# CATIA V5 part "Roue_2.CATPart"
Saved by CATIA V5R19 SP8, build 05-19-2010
Part number: Roue 2
Nomenclature: 70_R2
Bounding box of the stored display mesh (mm): x -20.76 to 20.76, y -20.76 to 20.76, z -2.4 to 8
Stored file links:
  C:\Users\rphgr\Desktop\0_Tapis_TC520B_vitesse\Roue_2.CATPart
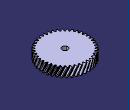
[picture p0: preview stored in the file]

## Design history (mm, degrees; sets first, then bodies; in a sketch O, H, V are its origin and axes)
External parameters (linked from other documents)
  External.Module = 0.9 mm
  External.Z = 40
  External.DiamPrimitif = 39.7216 mm {= External.ModuleApparent*External.Z}
  External.AnglePression = 20 deg
  External.x = 0
  External.DeportDenture = 0 mm {= External.x *External.ModuleApparent}
  External.DiamBase = 37.3261 mm {= External.DiamPrimitif *cos(External.AnglePression )}
  External.DiamPied = 37.4716 mm {= External.DiamPrimitif -2.5*External.Module +2*External.DeportDenture}
  External.DiamTete = 41.5216 mm {= External.DiamPrimitif +2*External.Module +2*External.DeportDenture}
  External.PhiPrimitif = 0.854 deg {= atan((sin(External.ThetaPrimitif*1rad)-External.ThetaPrimitif*cos(External.ThetaPrimitif*1rad))/(cos(External.ThetaPrimitif*1rad)+External.ThetaPrimitif*sin(External.ThetaPrimitif*1rad)))}
  External.PhiTete = 1.94 deg {= atan((sin(External.ThetaTete*1rad)-External.ThetaTete*cos(External.ThetaTete*1rad))/(cos(External.ThetaTete*1rad)+External.ThetaTete*sin(External.ThetaTete*1rad)))}
  External.PhiSymetrie = 2.25 deg {= 180*1 deg/(2*External.Z )}
  External.CongePied = 0.342 mm {= 0.38*External.Module}
  External.AlphaCopie = 9 deg {= 360*1 deg/External.Z}
  External.AlphaSymetrieCopie = 4.5 deg {= External.AlphaCopie /2}
  External.LargeurDenture = 8 mm {= External.LargeurDent}
  External.ThetaPrimitif = 0.36397 {= sqrt(abs((External.DiamPrimitif*External.DiamPrimitif)/(External.DiamBase *External.DiamBase )-1))}
  External.ThetaTete = 0.487275 {= sqrt(abs((External.DiamTete*External.DiamTete)/(External.DiamBase *External.DiamBase )-1) )}
  External.Di = 38.5239 mm {= (External.DiamBase +External.DiamPrimitif )/2}
  External.Thetai = 0.255358 {= sqrt(abs((External.Di*External.Di)/(External.DiamBase*External.DiamBase)-1))}
  External.Phii = 0.3061 deg {= atan((sin(External.Thetai*1rad)-External.Thetai*cos(External.Thetai*1rad))/(cos(External.Thetai*1rad)+External.Thetai*sin(External.Thetai*1rad)))}
  External.Dj = 40.6216 mm {= (External.DiamTete+External.DiamPrimitif)/2}
  External.Thetaj = 0.429388 {= sqrt(abs((External.Dj*External.Dj)/(External.DiamBase*External.DiamBase)-1))}
  External.Phij = 1.364 deg {= atan((sin(External.Thetaj*1rad)-External.Thetaj*cos(External.Thetaj*1rad))/(cos(External.Thetaj*1rad)+External.Thetaj*sin(External.Thetaj*1rad)))}
  External.Dk = 37.925 mm {= (External.Di+External.DiamBase)/2}
  External.Thetak = 0.179851 {= sqrt(abs((External.Dk*External.Dk)/(External.DiamBase*External.DiamBase)-1))}
  External.Phik = 0.109 deg {= atan((sin(External.Thetak*1rad)-External.Thetak*cos(External.Thetak*1rad))/(cos(External.Thetak*1rad)+External.Thetak*sin(External.Thetak*1rad)))}
  External.Dl = 39.1227 mm {= (External.DiamPrimitif+External.Di)/2}
  External.Thetal = 0.31398 {= sqrt(abs((External.Dl*External.Dl)/(External.DiamBase*External.DiamBase)-1))}
  External.Phil = 0.5585 deg {= atan((sin(External.Thetal*1rad)-External.Thetal*cos(External.Thetal*1rad))/(cos(External.Thetal*1rad)+External.Thetal*sin(External.Thetal*1rad)))}
  External.Dm = 40.1716 mm {= (External.Dj+External.DiamPrimitif)/2}
  External.Thetam = 0.397843 {= sqrt(abs((External.Dm*External.Dm)/(External.DiamBase*External.DiamBase)-1))}
  External.Phim = 1.0999 deg {= atan((sin(External.Thetam*1rad)-External.Thetam*cos(External.Thetam*1rad))/(cos(External.Thetam*1rad)+External.Thetam*sin(External.Thetam*1rad)))}
  External.Dn = 41.0716 mm {= (External.DiamTete+External.Dj)/2}
  External.Thetan = 0.459086 {= sqrt(abs((External.Dn*External.Dn)/(External.DiamBase*External.DiamBase)-1))}
  External.Phin = 1.6445 deg {= atan((sin(External.Thetan*1rad)-External.Thetan*cos(External.Thetan*1rad))/(cos(External.Thetan*1rad)+External.Thetan*sin(External.Thetan*1rad)))}
  External.AngleHelice = 25 deg
  External.ModuleApparent = 0.993 mm {= External.Module /cos(External.AngleHelice )}
  External.SensDenture = 1
  External.LargeurDent = 8 mm
Body1 (main body)
  Sketch1 "EsquisseDent" on xy-plane, origin (0, 0, 0), H (1, 0, 0), V (0, 1, 0)
    construction circle A1 centre (0, 0) radius 19.8608
    construction circle A2 centre (0, 0) radius 18.663
    construction circle A3 centre (0, 0) radius 18.7358
    construction circle A4 centre (0, 0) radius 20.7608
    point P1 (18.663, 0)
    construction line L1 (18.663, 0) -> (0, 0)
    point P2 (19.8586, 0.296)
    construction line L2 (19.8586, 0.296) -> (0, 0)
    point P3 (20.7489, 0.7028)
    construction line L3 (20.7489, 0.7028) -> (0, 0)
    construction line L4 (18.663, 0) -> (18.663, 3.9367)
    point P4 (18.663, 0)
    point P6 (17.4675, 0.296)
    construction line L5 (20.7489, 0.7028) -> (19.8586, 0.296)
    point P7 (20.3037, 0.4994)
    point P8 (17.0223, 0.4994)
    spline S1 through (17.0223, 0.4994) (17.4675, 0.296) (18.663, 0) (18.9625, 0.0361) (19.2617, 0.1029) (19.5604, 0.1907) (19.8586, 0.296) (20.0821, 0.3856) (20.305, 0.4835) (20.5273, 0.5893) (20.7489, 0.7028)
    construction line L6 (0, 0) -> (5.2667, 0.2856)
    spline S2 through (16.9765, 1.3443) (17.3971, 1.5946) (18.5536, 2.0182) (18.8552, 2.0147) (19.1598, 1.9806) (19.4664, 1.9257) (19.7742, 1.8532) (20.006, 1.7883) (20.2383, 1.7151) (20.4707, 1.6339) (20.7032, 1.545)
    arc A5 centre (19.0756, -0.2906) radius 0.342 from (19.01, 0.045) to (18.7336, -0.2854) ccw
    point P11 (18.7336, -0.2854)
    arc A6 centre (0, 0) radius 20.7608 from (20.7489, 0.7028) to (20.7032, 1.545) ccw
    point P13 (20.7032, 1.545)
    arc A7 centre (18.9323, 2.3517) radius 0.342 from (18.5929, 2.3096) to (18.9034, 2.0109) ccw
    point P15 (18.5929, 2.3096)
    construction line L7 (0, 0) -> (4.2456, 0.5668)
    construction line L8 (0, 0) -> (5.1243, -0.1249)
    point P19 (18.571, 2.4792)
    arc A8 centre (0, 0) radius 18.7358 from (18.5929, 2.3096) to (18.571, 2.4792) ccw
    point P20 (18.7302, -0.4565)
    arc A9 centre (0, 0) radius 18.7358 from (18.7302, -0.4565) to (18.7336, -0.2854) ccw
    line L9 (18.571, 2.4792) -> (0, 0)
    line L10 (18.7302, -0.4565) -> (0, 0)
    construction circle A10 centre (0, 0) radius 19.2619
    construction line L11 (0, 0) -> (2.5698, 0.0137)
    point P22 (19.2617, 0.1029)
    construction circle A11 centre (0, 0) radius 20.3108
    construction line L12 (0, 0) -> (4.0179, 0.0957)
    point P24 (20.305, 0.4835)
    point P25 (20.305, 0.4835)
    point P26 (20.2383, 1.7151)
    point P27 (19.1598, 1.9806)
    construction circle A12 centre (0, 0) radius 18.9625
    construction line L13 (0, 0) -> (48.2618, 0.0918)
    point P29 (18.8552, 2.0147)
    construction line L14 (0, 0) -> (63.8846, 3.4643)
    point P31 (18.9625, 0.0361)
    construction circle A13 centre (0, 0) radius 19.5614
    construction line L15 (0, 0) -> (57.3607, 0.5591)
    point P33 (19.5604, 0.1907)
    point P34 (19.4664, 1.9257)
    construction circle A14 centre (0, 0) radius 20.0858
    construction line L16 (0, 0) -> (65.6986, 1.2614)
    point P36 (20.0821, 0.3856)
    point P37 (20.006, 1.7883)
    construction circle A15 centre (0, 0) radius 20.5358
    axis line L17 (0, 0) -> (59.3265, 1.7033)
    point P39 (20.4707, 1.6339)
    point P40 (20.5273, 0.5893)
    point P42 (17.0223, 0.4994)
    point P43 (17.4675, 0.296)
    point P44 (18.663, 0)
    point P45 (19.8586, 0.296)
    point P46 (20.7489, 0.7028)
    point P47 (20.7032, 1.545)
    point P48 (16.9765, 1.3443)
    point P49 (19.7742, 1.8532)
    point P50 (18.5536, 2.0182)
    point P51 (17.3971, 1.5946)
    point P52 (19.2617, 0.1029)
    point P53 (20.305, 0.4835)
    point P54 (19.1598, 1.9806)
    point P55 (20.2383, 1.7151)
    point P56 (18.9625, 0.0361)
    point P57 (18.8552, 2.0147)
    point P58 (19.5604, 0.1907)
    point P59 (19.4664, 1.9257)
    point P60 (20.0821, 0.3856)
    point P61 (20.006, 1.7883)
    point P62 (20.5273, 0.5893)
    point P63 (20.4707, 1.6339)
    radius A1 = 19.8608 {= External.DiamPrimitif /2}
    radius A2 = 18.663 {= External.DiamBase /2}
    radius A3 = 18.7358 {= External.DiamPied /2}
    radius A4 = 20.7608 {= External.DiamTete /2}
    angle L2 L1 = 0.854 {= External.PhiPrimitif}
    angle L3 L1 = 1.94 {= External.PhiTete}
    angle L4 L1 = 90
    radius A5 = 0.342 {= External.CongePied}
    radius A7 = 0.342 {= External.CongePied}
    angle L7 L6 = 4.5 {= External.AlphaSymetrieCopie}
    angle L2 L6 = 2.25 {= External.PhiSymetrie}
    radius A10 = 19.2619 {= External.Di /2}
    angle L11 L1 = 0.3061 {= External.Phii}
    radius A11 = 20.3108 {= External.Dj /2}
    angle L12 L1 = 1.364 {= External.Phij}
    radius A12 = 18.9625 {= External.Dk/2}
    angle L13 L1 = 0.109 {= External.Phik}
    angle L14 L2 = 2.25 {= External.PhiSymetrie}
    radius A13 = 19.5614 {= External.Dl /2}
    angle L15 L1 = 0.5585 {= External.Phil}
    radius A14 = 20.0858 {= External.Dm /2}
    angle L16 L1 = 1.0999 {= External.Phim}
    radius A15 = 20.5358 {= External.Dn/2}
    angle L17 L1 = 1.6445 {= External.Phin}
    coincidence: P1 A2, P1 H, P2 A1, P3 A4, P4 A2, P7 L5, P42 P8, P43 P6, P44 P1, P45 L5, P45 L2, P46 L5, P46 L3, P11 A3, P47 P13, P15 A3, P19 L7, P19 A3, P20 L8, P20 A3, P3 P46, P22 L11, P22 A10, P52 P22, P24 L12, P24 A11, P53 P24, P25 P53, P54 P27, P55 P26, P31 L13, P31 A12, P56 P31, P57 P29, P33 L15, P33 A13, P58 P33, P59 P34, P36 L16, P36 A14, P60 P36, P61 P37, P40 L17, P40 A15, P62 P40, P63 P39, O L9, O L10
    horizontal: L1 H
    tangency: L4 A2, A5 A3, A5 S1, A7 A3, A7 S2, A8 A5, A9 A5
    symmetry: P6 P2 L4, P8 P7 L4, P46 P47 L6, P42 P48 L6, P45 P49 L6, P44 P50 L6, P43 P51 L6, L8 L7 L6, P26 P25 L6, P27 P22 L6, P29 P31 L14, P34 P33 L14, P37 P36 L14, P39 P40 L14
    midpoint: P7 L5
    parallelism: L9 L7, L10 L8
    concentricity: A10 A2, A11 A1
  Translate1: ToTransfor Sketch1, Direction (0, 0, 1), Length 8 {= External.LargeurDenture}
  Rotate1: ToTransfor Translate1, Axis Z axis, Angle 10.6379 {= External.SensDenture *atan(2*External.LargeurDenture/External.DiamPrimitif*tan(External.AngleHelice))}
  Translate2: ToTransfor Sketch1, Direction (0, 0, 1), Length 4 {= External.LargeurDenture/2}
  Rotate2: ToTransfor Translate2, Axis Z axis, Angle 5.3652 {= External.SensDenture *atan(External.LargeurDenture/(External.DiamPrimitif)*tan(External.AngleHelice))}
  Translate3: ToTransfor Sketch1, Direction (0, 0, 1), Length 6 {= 3/4*External.LargeurDenture}
  Rotate3: ToTransfor Translate3, Axis Z axis, Angle 8.0186 {= External.SensDenture*atan(3*External.LargeurDenture/(2*External.DiamPrimitif)*tan(External.AngleHelice))}
  Translate4: ToTransfor Sketch1, Direction (0, 0, 1), Length 2 {= External.LargeurDenture/4}
  Rotate4: ToTransfor Translate4, Axis Z axis, Angle 2.6885 {= External.SensDenture*atan(External.LargeurDenture/(2*External.DiamPrimitif)*tan(External.AngleHelice))}
  Loft1: solid, Sections (Sketch1; Rotate4; Rotate2; Rotate3; Rotate1)
  CircPattern1: of the body so far, instances 40 {= External.Z}, angular step 9 {= External.AlphaCopie}, axis from Z axis
  Sketch2 on face of CircPattern1, origin (-2.3642, -1.7711, 0), H (1, 0, 0), V (0, -1, 0)
    point P1 (2.3634, -1.7718)
    reference intersected arc E1 centre (2.3634, -1.7718) radius 20.7618 from (18.0961, 11.7758) to (17.5328, 12.4037) ccw from face of CircPattern1
    concentricity: P1 E1
  Hole1: placed by Sketch2, at (-0.0008, 0.0007, 0) direction (0, 0, 1), diameter 5, through (limit type 3), counterbore diameter 33, counterbore depth 1.6
  Sketch3 on face of Hole1, origin (0, 0, 1.6), H (1, 0, 0), V (0, -1, 0)
    circle A1 centre (0, 0) radius 7.665
    projected circle E1 centre (-0.0008, -0.0007) radius 2.5 from edge [face of Hole1 | face of Hole1]
    radius A1 = 7.665
  Pad1: profile Sketch3, direction (0, 0, -1), length 3
  Sketch4 on end face of Pad1, origin (0, 0, -1.4), H (1, 0, 0), V (0, -1, 0)
    circle A1 centre (0, 0) radius 4.5
    projected circle E1 centre (-0.0008, -0.0007) radius 2.5 from edge [end face of Pad1 | face of Pad1]
    radius A1 = 4.5
  Pad2: profile Sketch4, direction (0, 0, -1), length 1
  Fillet1: radius 0.9, on edge [face of Pad2 from Sketch4.A1 | end face of Pad2]; edge [end face of Pad2 | face of Pad2]
  Sketch5 on face of CircPattern1, origin (0, 0, 8), H (1, 0, 0), V (0, 1, 0)
    circle A1 centre (0, 0) radius 16.5
    circle A2 centre (0, 0) radius 7.65
    radius A2 = 7.65
    radius A1 = 16.5
  Pocket1: profile Sketch5, direction (0, 0, -1), length 3
  Plane1: type Offset, RefPlane xy-plane, Offset 8 {= External.LargeurDenture}, reversed
Current feature: Fillet1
